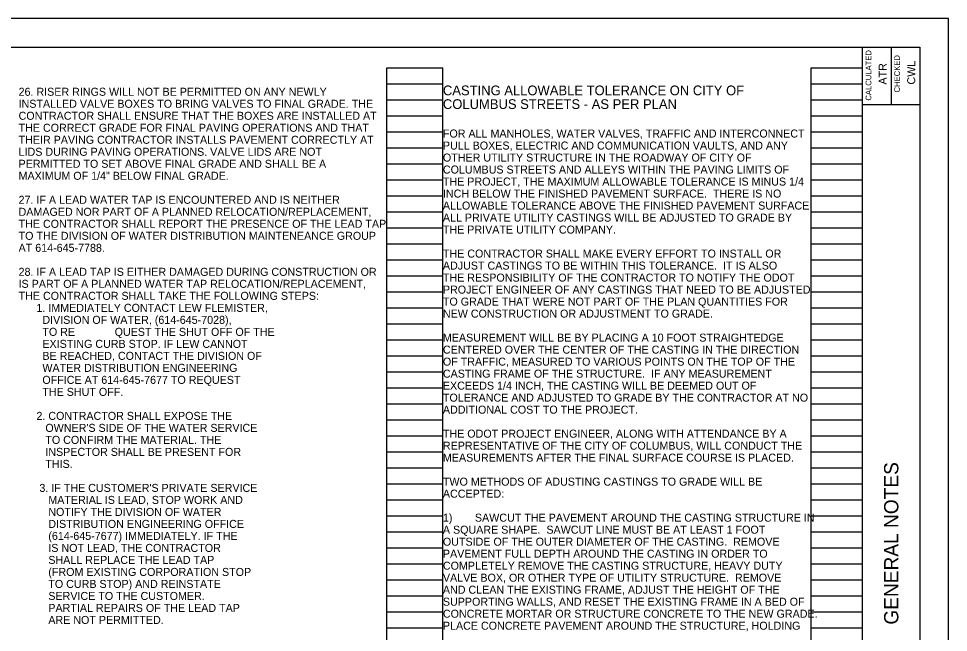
# Model space of a CAD drawing. Extents: x 0 to 34, y 0 to 22.
# Drawn here: x 17.74 to 34, y 11.26 to 22 of the extents above; entities that cross this region are included whole.
import ezdxf

# ---------------------------------------------------------------- set-up
doc = ezdxf.new("R2010")
doc.units = 0
for name, color, linetype in [('SC_Scratch1', 7, 'Continuous'), ('SH_Border', 7, 'Continuous'), ('SH_Cut_Line', 7, 'Continuous'), ('SH_Data', 7, 'Continuous'), ('SH_Text', 7, 'Continuous'), ('TX_P_Misc', 7, 'Continuous')]:
    doc.layers.add(name, color=color, linetype=linetype)

msp = doc.modelspace()

# ---------------------------------------------------------------- linework, layer by layer
at = {"layer": 'SC_Scratch1'}
for p, q in [((24.18, 0.98), (24.18, 21.14)), ((24.18, 21.14), (25.16, 21.14)), ((25.16, 0.98), (25.16, 21.14)), ((31.6, 0.98), (31.6, 21.14)), ((31.6, 21.14), (32.5, 21.14)), ((32.5, 0.98), (32.5, 21.14)), ((24.18, 20.86), (25.16, 20.86)), ((31.6, 20.86), (32.5, 20.86)), ((24.18, 20.58), (25.16, 20.58)), ((31.6, 20.58), (32.5, 20.58)), ((24.18, 20.3), (25.16, 20.3)), ((31.6, 20.3), (32.5, 20.3)), ((24.18, 20.02), (25.16, 20.02)), ((31.6, 20.02), (32.5, 20.02)), ((24.18, 19.74), (25.16, 19.74)), ((31.6, 19.74), (32.5, 19.74)), ((24.18, 19.46), (25.16, 19.46)), ((31.6, 19.46), (32.5, 19.46)), ((24.18, 19.18), (25.16, 19.18)), ((31.6, 19.18), (32.5, 19.18)), ((24.18, 18.9), (25.16, 18.9)), ((31.6, 18.9), (32.5, 18.9)), ((24.18, 18.62), (25.16, 18.62)), ((31.6, 18.62), (32.5, 18.62)), ((24.18, 18.34), (25.16, 18.34)), ((31.6, 18.34), (32.5, 18.34)), ((24.18, 18.06), (25.16, 18.06)), ((31.6, 18.06), (32.5, 18.06)), ((24.18, 17.78), (25.16, 17.78)), ((31.6, 17.78), (32.5, 17.78)), ((24.18, 17.5), (25.16, 17.5)), ((31.6, 17.5), (32.5, 17.5)), ((24.18, 17.22), (25.16, 17.22)), ((31.6, 17.22), (32.5, 17.22)), ((24.18, 16.94), (25.16, 16.94)), ((31.6, 16.94), (32.5, 16.94)), ((24.18, 16.66), (25.16, 16.66)), ((31.6, 16.66), (32.5, 16.66)), ((24.18, 16.38), (25.16, 16.38)), ((31.6, 16.38), (32.5, 16.38)), ((24.18, 16.1), (25.16, 16.1)), ((31.6, 16.1), (32.5, 16.1)), ((24.18, 15.82), (25.16, 15.82)), ((31.6, 15.82), (32.5, 15.82)), ((24.18, 15.54), (25.16, 15.54)), ((31.6, 15.54), (32.5, 15.54)), ((24.18, 15.26), (25.16, 15.26)), ((31.6, 15.26), (32.5, 15.26)), ((24.18, 14.98), (25.16, 14.98)), ((31.6, 14.98), (32.5, 14.98)), ((24.18, 14.7), (25.16, 14.7)), ((31.6, 14.7), (32.5, 14.7)), ((24.18, 14.42), (25.16, 14.42)), ((31.6, 14.42), (32.5, 14.42)), ((24.18, 14.14), (25.16, 14.14)), ((31.6, 14.14), (32.5, 14.14)), ((24.18, 13.86), (25.16, 13.86)), ((31.6, 13.86), (32.5, 13.86)), ((24.18, 13.58), (25.16, 13.58)), ((31.6, 13.58), (32.5, 13.58)), ((24.18, 13.3), (25.16, 13.3)), ((31.6, 13.3), (32.5, 13.3)), ((24.18, 13.02), (25.16, 13.02)), ((31.6, 13.02), (32.5, 13.02)), ((24.18, 12.74), (25.16, 12.74)), ((31.6, 12.74), (32.5, 12.74)), ((24.18, 12.46), (25.16, 12.46)), ((31.6, 12.46), (32.5, 12.46)), ((24.18, 12.18), (25.16, 12.18)), ((31.6, 12.18), (32.5, 12.18)), ((24.18, 11.9), (25.16, 11.9)), ((31.6, 11.9), (32.5, 11.9)), ((24.18, 11.62), (25.16, 11.62)), ((31.6, 11.62), (32.5, 11.62)), ((24.18, 11.34), (25.16, 11.34)), ((31.6, 11.34), (32.5, 11.34))]:
    msp.add_line(p, q, dxfattribs=at)
at = {"layer": 'SH_Border'}
for p, q in [((32.5, 0.5), (32.5, 21.5)), ((33, 21.5), (33, 20.5)), ((32.5, 20.5), (33.5, 20.5))]:
    msp.add_line(p, q, dxfattribs=at)
msp.add_lwpolyline([(2, 21.5), (33.5, 21.5), (33.5, 0.5), (2, 0.5)], close=True, dxfattribs=at)
at = {"layer": 'SH_Cut_Line'}
msp.add_lwpolyline([(0, 0), (34, 0), (34, 22), (0, 22)], close=True, dxfattribs=at)

# ---------------------------------------------------------------- texts
at = {"layer": 'SH_Data'}
for s, height, p in [('CALCULATED', 0.1, (32.652, 20.565)), ('CHECKED', 0.1, (33.152, 20.708)), ('ATR', 0.14, (32.92, 20.846)), ('CWL', 0.14, (33.42, 20.846)), ('GENERAL NOTES', 0.25, (33.125, 11.398))]:
    msp.add_text(s, height=height, rotation=90, dxfattribs=at).set_placement(p)
at = {"layer": 'SH_Text'}
for s, p in [('26. RISER RINGS WILL NOT BE PERMITTED ON ANY NEWLY ', (17.74, 20.65)), ('INSTALLED VALVE BOXES TO BRING VALVES TO FINAL GRADE. THE ', (17.74, 20.44)), ('CONTRACTOR SHALL ENSURE THAT THE BOXES ARE INSTALLED AT ', (17.74, 20.23)), ('THE CORRECT GRADE FOR FINAL PAVING OPERATIONS AND THAT ', (17.74, 20.02)), ('FOR ALL MANHOLES, WATER VALVES, TRAFFIC AND INTERCONNECT ', (25.16, 19.919)), ('THEIR PAVING CONTRACTOR INSTALLS PAVEMENT CORRECTLY AT ', (17.74, 19.81)), ('PULL BOXES, ELECTRIC AND COMMUNICATION VAULTS, AND ANY ', (25.16, 19.709)), ('LIDS DURING PAVING OPERATIONS. VALVE LIDS ARE NOT ', (17.74, 19.6)), ('PERMITTED TO SET ABOVE FINAL GRADE AND SHALL BE A ', (17.74, 19.39)), ('OTHER UTILITY STRUCTURE IN THE ROADWAY OF CITY OF ', (25.16, 19.499)), ('COLUMBUS STREETS AND ALLEYS WITHIN THE PAVING LIMITS OF ', (25.16, 19.289)), ('MAXIMUM OF 1/4" BELOW FINAL GRADE.', (17.74, 19.18)), ('THE PROJECT, THE MAXIMUM ALLOWABLE TOLERANCE IS MINUS 1/4 ', (25.16, 19.079)), ('27. IF A LEAD WATER TAP IS ENCOUNTERED AND IS NEITHER ', (17.74, 18.76)), ('INCH BELOW THE FINISHED PAVEMENT SURFACE.  THERE IS NO ', (25.16, 18.869)), ('ALLOWABLE TOLERANCE ABOVE THE FINISHED PAVEMENT SURFACE. ', (25.16, 18.659)), ('DAMAGED NOR PART OF A PLANNED RELOCATION/REPLACEMENT, ', (17.74, 18.55)), ('ALL PRIVATE UTILITY CASTINGS WILL BE ADJUSTED TO GRADE BY ', (25.16, 18.449)), ('THE CONTRACTOR SHALL REPORT THE PRESENCE OF THE LEAD TAP ', (17.74, 18.34)), ('THE PRIVATE UTILITY COMPANY.', (25.16, 18.239)), ('TO THE DIVISION OF WATER DISTRIBUTION MAINTENEANCE GROUP ', (17.74, 18.13)), ('AT 614-645-7788.', (17.74, 17.92)), ('THE CONTRACTOR SHALL MAKE EVERY EFFORT TO INSTALL OR ', (25.16, 17.819)), ('ADJUST CASTINGS TO BE WITHIN THIS TOLERANCE.  IT IS ALSO ', (25.16, 17.609)), ('28. IF A LEAD TAP IS EITHER DAMAGED DURING CONSTRUCTION OR ', (17.74, 17.5)), ('IS PART OF A PLANNED WATER TAP RELOCATION/REPLACEMENT, ', (17.74, 17.29)), ('THE RESPONSIBILITY OF THE CONTRACTOR TO NOTIFY THE ODOT ', (25.16, 17.399)), ('PROJECT ENGINEER OF ANY CASTINGS THAT NEED TO BE ADJUSTED ', (25.16, 17.189)), ('THE CONTRACTOR SHALL TAKE THE FOLLOWING STEPS:', (17.74, 17.08)), ('TO GRADE THAT WERE NOT PART OF THE PLAN QUANTITIES FOR ', (25.16, 16.979)), ('      1. IMMEDIATELY CONTACT LEW FLEMISTER, ', (17.74, 16.87)), ('NEW CONSTRUCTION OR ADJUSTMENT TO GRADE.', (25.16, 16.769)), ('        DIVISION OF WATER, (614-645-7028),   ', (17.74, 16.66)), ('        TO RE', (17.74, 16.45)), ('QUEST THE SHUT OFF OF THE', (19.42, 16.45)), ('MEASUREMENT WILL BE BY PLACING A 10 FOOT STRAIGHTEDGE ', (25.16, 16.349)), ('        EXISTING CURB STOP. IF LEW CANNOT', (17.74, 16.24)), ('CENTERED OVER THE CENTER OF THE CASTING IN THE DIRECTION ', (25.16, 16.139)), ('        BE REACHED, CONTACT THE DIVISION OF', (17.74, 16.03)), ('        WATER DISTRIBUTION ENGINEERING ', (17.74, 15.82)), ('OF TRAFFIC, MEASURED TO VARIOUS POINTS ON THE TOP OF THE ', (25.16, 15.929)), ('CASTING FRAME OF THE STRUCTURE.  IF ANY MEASUREMENT ', (25.16, 15.719)), ('        OFFICE AT 614-645-7677 TO REQUEST ', (17.74, 15.61)), ('EXCEEDS 1/4 INCH, THE CASTING WILL BE DEEMED OUT OF ', (25.16, 15.509)), ('        THE SHUT OFF.', (17.74, 15.4)), ('TOLERANCE AND ADJUSTED TO GRADE BY THE CONTRACTOR AT NO ', (25.16, 15.299)), ('      2. CONTRACTOR SHALL EXPOSE THE ', (17.74, 14.98)), ('ADDITIONAL COST TO THE PROJECT.', (25.16, 15.089)), ("         OWNER'S SIDE OF THE WATER SERVICE", (17.74, 14.77)), ('THE ODOT PROJECT ENGINEER, ALONG WITH ATTENDANCE BY A ', (25.16, 14.669)), ('         TO CONFIRM THE MATERIAL. THE ', (17.74, 14.56)), ('         INSPECTOR SHALL BE PRESENT FOR ', (17.74, 14.35)), ('REPRESENTATIVE OF THE CITY OF COLUMBUS, WILL CONDUCT THE ', (25.16, 14.459)), ('MEASUREMENTS AFTER THE FINAL SURFACE COURSE IS PLACED. ', (25.16, 14.249)), ('         THIS.', (17.74, 14.14)), ("       3. IF THE CUSTOMER'S PRIVATE SERVICE", (17.74, 13.72)), ('TWO METHODS OF ADUSTING CASTINGS TO GRADE WILL BE ', (25.16, 13.829)), ('ACCEPTED:', (25.16, 13.619)), ('          MATERIAL IS LEAD, STOP WORK AND ', (17.74, 13.51)), ('          NOTIFY THE DIVISION OF WATER ', (17.74, 13.3)), ('1)', (25.16, 13.199)), ('SAWCUT THE PAVEMENT AROUND THE CASTING STRUCTURE IN ', (25.72, 13.199)), ('          DISTRIBUTION ENGINEERING OFFICE ', (17.74, 13.09)), ('          (614-645-7677) IMMEDIATELY. IF THE ', (17.74, 12.88)), ('A SQUARE SHAPE.  SAWCUT LINE MUST BE AT LEAST 1 FOOT ', (25.16, 12.989)), ('OUTSIDE OF THE OUTER DIAMETER OF THE CASTING.  REMOVE ', (25.16, 12.779)), ('          IS NOT LEAD, THE CONTRACTOR ', (17.74, 12.67)), ('PAVEMENT FULL DEPTH AROUND THE CASTING IN ORDER TO ', (25.16, 12.569)), ('          SHALL REPLACE THE LEAD TAP ', (17.74, 12.46)), ('          (FROM EXISTING CORPORATION STOP', (17.74, 12.25)), ('COMPLETELY REMOVE THE CASTING STRUCTURE, HEAVY DUTY ', (25.16, 12.359)), ('VALVE BOX, OR OTHER TYPE OF UTILITY STRUCTURE.  REMOVE ', (25.16, 12.149)), ('          TO CURB STOP) AND REINSTATE ', (17.74, 12.04)), ('AND CLEAN THE EXISTING FRAME, ADJUST THE HEIGHT OF THE ', (25.16, 11.939)), ('          SERVICE TO THE CUSTOMER.  ', (17.74, 11.83)), ('SUPPORTING WALLS, AND RESET THE EXISTING FRAME IN A BED OF ', (25.16, 11.729)), ('          PARTIAL REPAIRS OF THE LEAD TAP', (17.74, 11.62)), ('          ARE NOT PERMITTED. ', (17.74, 11.41)), ('CONCRETE MORTAR OR STRUCTURE CONCRETE TO THE NEW GRADE. ', (25.16, 11.519)), ('PLACE CONCRETE PAVEMENT AROUND THE STRUCTURE, HOLDING ', (25.16, 11.309))]:
    msp.add_text(s, height=0.14, dxfattribs=at).set_placement(p)
at = {"layer": 'TX_P_Misc'}
for s, p in [('CASTING ALLOWABLE TOLERANCE ON CITY OF ', (25.16, 20.659)), ('COLUMBUS STREETS - AS PER PLAN', (25.16, 20.419))]:
    msp.add_text(s, height=0.17, dxfattribs=at).set_placement(p)

doc.saveas('drawing.dxf')
